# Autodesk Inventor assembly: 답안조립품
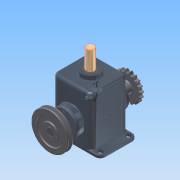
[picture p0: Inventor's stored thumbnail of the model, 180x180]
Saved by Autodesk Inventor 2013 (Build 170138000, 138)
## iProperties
Created: 2015-03
Part Number: 답안조립품
Document SubType Name: Assembly
Designer: Administrator
Mass: 8579 g
Surface Area: 4386.42 cm^2
Volume: 1982.5 cm^3
Density: 4.32736 g/cm^3
Author: Administrator
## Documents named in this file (15)
- C:\Documents and Settings\Administrator\바탕 화면\350305V1036\답안조립품.iam
- C:\Documents and Settings\Administrator\바탕 화면\350305V1036\본체.ipt
- C:\Documents and Settings\Administrator\바탕 화면\350305V1036\베어링 6205.ipt
- C:\Documents and Settings\Administrator\바탕 화면\350305V1036\커버.ipt
- C:\Documents and Settings\Administrator\바탕 화면\350305V1036\체인 스프로킷.ipt
- C:\Documents and Settings\Administrator\바탕 화면\350305V1036\편심축.ipt
- C:\Documents and Settings\Administrator\바탕 화면\350305V1036\키 8x8.ipt
- C:\Documents and Settings\Administrator\바탕 화면\350305V1036\오일실.ipt
- C:\Documents and Settings\Administrator\바탕 화면\350305V1036\멈춤나사 M5x0.5.ipt
- C:\Documents and Settings\Administrator\바탕 화면\350305V1036\M4x0.5.ipt
- C:\Documents and Settings\Administrator\바탕 화면\350305V1036\멈춤링.ipt
- C:\Documents and Settings\Administrator\바탕 화면\350305V1036\V-벨트풀리.ipt
- C:\Documents and Settings\Administrator\바탕 화면\350305V1036\부시.ipt
- C:\Documents and Settings\Administrator\바탕 화면\350305V1036\슬라이드.ipt
- C:\Documents and Settings\Administrator\바탕 화면\350305V1036\7-가변스프링.ipt
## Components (9 placed, 4 different names)
1. 5-체인 스프로킷:1 — 플러쉬:2, 각도:2
2. V-벨트풀리:1 — 플러쉬:4, 각도:4
3. 7-가변스프링:1
4. M4x0.5:1
5. M4x0.5:2
6. M4x0.5:3
7. M4x0.5:4
8. M4x0.5:5
9. M4x0.5:6
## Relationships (4: Flush 2, Angle 2)
- 플러쉬:2 [Flush]: 5-체인 스프로킷:1
- 각도:2 [Angle]: 5-체인 스프로킷:1
- 플러쉬:4 [Flush]: V-벨트풀리:1
- 각도:4 [Angle]: V-벨트풀리:1
